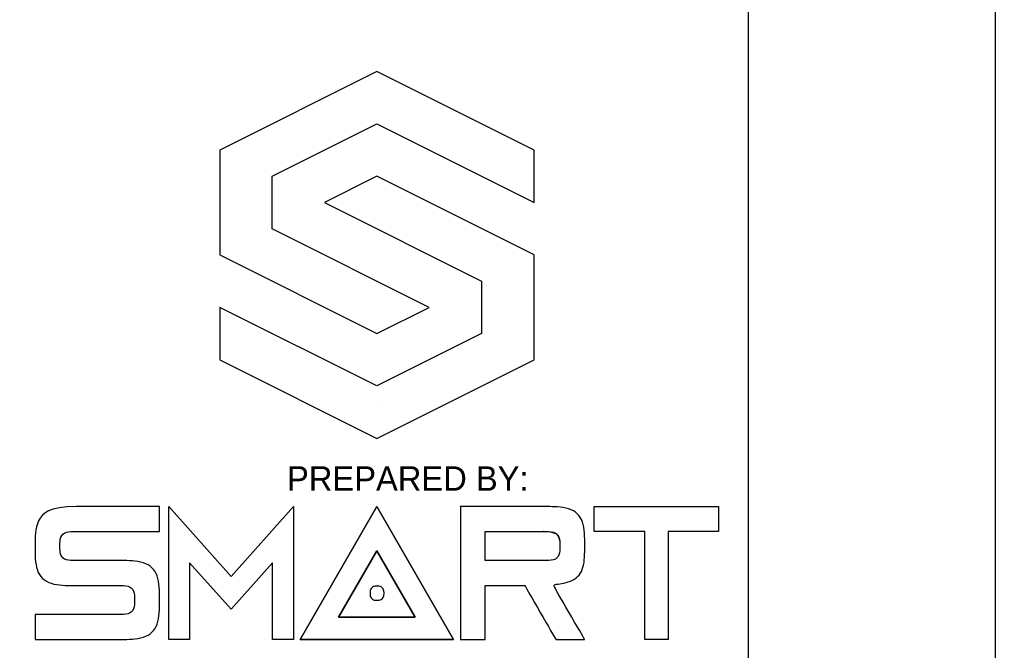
# Model space of a CAD drawing. Extents: x 0 to 34, y 0 to 22.
# Drawn here: x 32.028 to 34, y 3.5 to 4.774 of the extents above; entities that cross this region are included whole.
import ezdxf

# ---------------------------------------------------------------- set-up
doc = ezdxf.new("R2010")
doc.units = 0
for name, color, linetype in [('BORDER', 7, 'Continuous'), ('SH_Border', 7, 'Continuous'), ('SH_Cut_Line', 7, 'Continuous'), ('SH_Data', 7, 'Continuous')]:
    doc.layers.add(name, color=color, linetype=linetype)

msp = doc.modelspace()

# ---------------------------------------------------------------- linework, layer by layer
at = {"layer": 'BORDER'}
for p, q in [((32.75, 4.6694), (32.4325, 4.5106)), ((33.0676, 4.5106), (32.75, 4.6694)), ((32.5383, 4.4577), (32.75, 4.5635)), ((32.75, 4.5635), (33.0676, 4.4047)), ((32.4325, 4.5106), (32.4325, 4.2989)), ((33.0676, 4.4047), (33.0676, 4.5106)), ((32.5383, 4.3518), (32.5383, 4.4577)), ((32.75, 4.4577), (32.6442, 4.4047)), ((33.0676, 4.2989), (32.75, 4.4577)), ((32.6442, 4.4047), (32.9617, 4.246)), ((32.8559, 4.193), (32.5383, 4.3518)), ((32.4325, 4.2989), (32.75, 4.1401)), ((33.0676, 4.0872), (33.0676, 4.2989)), ((32.9617, 4.246), (32.9617, 4.1401)), ((32.75, 4.0343), (32.4325, 4.193)), ((32.4325, 4.193), (32.4325, 4.0872)), ((32.75, 4.1401), (32.8559, 4.193)), ((32.9617, 4.1401), (32.75, 4.0343)), ((32.4325, 4.0872), (32.75, 3.9284)), ((32.75, 3.9284), (33.0676, 4.0872)), ((32.3299, 3.5224), (32.3299, 3.7905)), ((32.3299, 3.7905), (32.4556, 3.6496)), ((32.4556, 3.6496), (32.5813, 3.7905)), ((32.5813, 3.7905), (32.5813, 3.5224)), ((33.1892, 3.7403), (33.1892, 3.7905)), ((33.1892, 3.7905), (33.4406, 3.7905)), ((33.4406, 3.7905), (33.4406, 3.7403)), ((33.2913, 3.7403), (33.1892, 3.7403)), ((33.2913, 3.5224), (33.2913, 3.7403)), ((33.4406, 3.7403), (33.3385, 3.7403)), ((33.3385, 3.7403), (33.3385, 3.5224)), ((32.3718, 3.6771), (32.3718, 3.5224)), ((32.4556, 3.5832), (32.3718, 3.6771)), ((32.5394, 3.6771), (32.4556, 3.5832)), ((32.5394, 3.5224), (32.5394, 3.6771)), ((32.3718, 3.5224), (32.3299, 3.5224)), ((32.5813, 3.5224), (32.5394, 3.5224)), ((33.3385, 3.5224), (33.2913, 3.5224))]:
    msp.add_line(p, q, dxfattribs=at)
for points in [[(32.75, 4.6694), (32.4325, 4.5106), (32.4325, 4.2989), (32.75, 4.1401), (32.8559, 4.193), (32.5383, 4.3518), (32.5383, 4.4577), (32.75, 4.5635), (33.0676, 4.4047), (33.0676, 4.5106), (32.75, 4.6694)], [(32.75, 3.9284), (33.0676, 4.0872), (33.0676, 4.2989), (32.75, 4.4577), (32.6442, 4.4047), (32.9617, 4.246), (32.9617, 4.1401), (32.75, 4.0343), (32.4325, 4.193), (32.4325, 4.0872), (32.75, 3.9284)], [(32.3718, 3.6771), (32.3718, 3.5224), (32.3299, 3.5224), (32.3299, 3.7905), (32.4556, 3.6496), (32.5813, 3.7905), (32.5813, 3.5224), (32.5394, 3.5224), (32.5394, 3.6771), (32.4556, 3.5832), (32.3718, 3.6771)], [(32.5953, 3.5224), (32.75, 3.7905), (32.9047, 3.5224), (32.5953, 3.5224)], [(33.2913, 3.7403), (33.1892, 3.7403), (33.1892, 3.7905), (33.4406, 3.7905), (33.4406, 3.7403), (33.3385, 3.7403), (33.3385, 3.5224), (33.2913, 3.5224), (33.2913, 3.7403)], [(32.6726, 3.5671), (32.8274, 3.5671), (32.75, 3.7011), (32.6726, 3.5671)]]:
    msp.add_lwpolyline(points, dxfattribs=at)
for points in [[(32.9047, 3.5224), (32.75, 3.7905), (32.5953, 3.5224)], [(32.75, 3.7011), (32.8274, 3.5671), (32.6726, 3.5671)]]:
    msp.add_lwpolyline(points, close=True, dxfattribs=at)
for points, degree in [([(32.1432, 3.7905), (32.1432, 3.7905), (32.3108, 3.7905), (32.3108, 3.7905), (32.3108, 3.7905), (32.3108, 3.7403), (32.3108, 3.7403), (32.3108, 3.7403), (32.1432, 3.7403), (32.1432, 3.7403), (32.1209, 3.7403), (32.1097, 3.7305), (32.1097, 3.7109), (32.1097, 3.6914), (32.1209, 3.6816), (32.1432, 3.6816), (32.1432, 3.6816), (32.227, 3.6816), (32.227, 3.6816), (32.2829, 3.6816), (32.3108, 3.6551), (32.3108, 3.602), (32.3108, 3.5489), (32.2829, 3.5224), (32.227, 3.5224), (32.227, 3.5224), (32.0594, 3.5224), (32.0594, 3.5224), (32.0594, 3.5224), (32.0594, 3.5727), (32.0594, 3.5727), (32.0594, 3.5727), (32.227, 3.5727), (32.227, 3.5727), (32.2494, 3.5727), (32.2605, 3.5824), (32.2605, 3.602), (32.2605, 3.6215), (32.2494, 3.6313), (32.227, 3.6313), (32.227, 3.6313), (32.1432, 3.6313), (32.1432, 3.6313), (32.0874, 3.6313), (32.0594, 3.6579), (32.0594, 3.7109), (32.0594, 3.764), (32.0874, 3.7905), (32.1432, 3.7905)], 3), ([(32.1432, 3.7905), (32.1432, 3.7905), (32.3108, 3.7905), (32.3108, 3.7905), (32.3108, 3.7905), (32.3108, 3.7403), (32.3108, 3.7403), (32.3108, 3.7403), (32.1432, 3.7403), (32.1432, 3.7403), (32.1209, 3.7403), (32.1097, 3.7305), (32.1097, 3.7109), (32.1097, 3.6914), (32.1209, 3.6816), (32.1432, 3.6816), (32.1432, 3.6816), (32.227, 3.6816), (32.227, 3.6816), (32.2829, 3.6816), (32.3108, 3.6551), (32.3108, 3.602), (32.3108, 3.5489), (32.2829, 3.5224), (32.227, 3.5224), (32.227, 3.5224), (32.0594, 3.5224), (32.0594, 3.5224), (32.0594, 3.5224), (32.0594, 3.5727), (32.0594, 3.5727), (32.0594, 3.5727), (32.227, 3.5727), (32.227, 3.5727), (32.2494, 3.5727), (32.2605, 3.5824), (32.2605, 3.602), (32.2605, 3.6215), (32.2494, 3.6313), (32.227, 3.6313), (32.227, 3.6313), (32.1432, 3.6313), (32.1432, 3.6313), (32.0874, 3.6313), (32.0594, 3.6579), (32.0594, 3.7109), (32.0594, 3.764), (32.0874, 3.7905), (32.1432, 3.7905)], 3), ([(32.9188, 3.7905), (32.9188, 3.7905), (32.9188, 3.5224), (32.9188, 3.5224)], 2), ([(32.9188, 3.5224), (32.9188, 3.5224), (32.969, 3.5224), (32.969, 3.5224), (32.969, 3.5224), (32.969, 3.6313), (32.969, 3.6313), (32.969, 3.6313), (33.0488, 3.6313), (33.0488, 3.6313), (33.0488, 3.6313), (33.1117, 3.5224), (33.1117, 3.5224), (33.1117, 3.5224), (33.1698, 3.5224), (33.1698, 3.5224), (33.1698, 3.5224), (33.1061, 3.6327), (33.1061, 3.6327), (33.1488, 3.6385), (33.1701, 3.6646), (33.1701, 3.7109), (33.1701, 3.764), (33.1422, 3.7905), (33.0863, 3.7905), (33.0863, 3.7905), (32.9188, 3.7905), (32.9188, 3.7905)], 3), ([(32.9188, 3.7905), (32.9188, 3.7905), (33.0863, 3.7905), (33.0863, 3.7905), (33.1422, 3.7905), (33.1701, 3.764), (33.1701, 3.7109), (33.1701, 3.6646), (33.1488, 3.6385), (33.1061, 3.6327), (33.1061, 3.6327), (33.1698, 3.5224), (33.1698, 3.5224), (33.1698, 3.5224), (33.1117, 3.5224), (33.1117, 3.5224), (33.1117, 3.5224), (33.0488, 3.6313), (33.0488, 3.6313), (33.0488, 3.6313), (32.969, 3.6313), (32.969, 3.6313), (32.969, 3.6313), (32.969, 3.5224), (32.969, 3.5224), (32.969, 3.5224), (32.9188, 3.5224), (32.9188, 3.5224), (32.9188, 3.5224), (32.9188, 3.7905), (32.9188, 3.7905)], 3), ([(32.969, 3.7403), (32.969, 3.7403), (33.0863, 3.7403), (33.0863, 3.7403)], 2), ([(33.0863, 3.7403), (33.1087, 3.7403), (33.1199, 3.7305), (33.1199, 3.7109), (33.1199, 3.6914), (33.1087, 3.6816), (33.0863, 3.6816), (33.0863, 3.6816), (32.969, 3.6816), (32.969, 3.6816), (32.969, 3.6816), (32.969, 3.7403), (32.969, 3.7403)], 3), ([(32.969, 3.7403), (32.969, 3.7403), (32.969, 3.6816), (32.969, 3.6816), (32.969, 3.6816), (33.0863, 3.6816), (33.0863, 3.6816), (33.1087, 3.6816), (33.1199, 3.6914), (33.1199, 3.7109), (33.1199, 3.7305), (33.1087, 3.7403), (33.0863, 3.7403), (33.0863, 3.7403), (32.969, 3.7403), (32.969, 3.7403)], 3), ([(32.7649, 3.6157), (32.7649, 3.6078), (32.7585, 3.6014), (32.7506, 3.6014), (32.7427, 3.6014), (32.7363, 3.6078), (32.7363, 3.6157), (32.7363, 3.6236), (32.7427, 3.63), (32.7506, 3.63), (32.7585, 3.63), (32.7649, 3.6236), (32.7649, 3.6157)], 3), ([(32.7649, 3.6157), (32.7649, 3.6078), (32.7585, 3.6014), (32.7506, 3.6014), (32.7427, 3.6014), (32.7363, 3.6078), (32.7363, 3.6157), (32.7363, 3.6236), (32.7427, 3.63), (32.7506, 3.63), (32.7585, 3.63), (32.7649, 3.6236), (32.7649, 3.6157)], 3)]:
    msp.add_open_spline(points, degree=degree, dxfattribs=at)
at = {"layer": 'SH_Border'}
msp.add_lwpolyline([(1.5, 21.5), (33.5, 21.5), (33.5, 0.5), (1.5, 0.5)], close=True, dxfattribs=at)
at = {"layer": 'SH_Cut_Line'}
msp.add_lwpolyline([(0, 0), (34, 0), (34, 22), (0, 22)], close=True, dxfattribs=at)
at = {"layer": 'SH_Data'}
msp.add_line((32.75, 4), (32.75, 4), dxfattribs=at)

# ---------------------------------------------------------------- texts
at = {"layer": 'BORDER'}
msp.add_text('PREPARED BY:', height=0.049387, dxfattribs=at).set_placement((32.5685, 3.8226))

doc.saveas('drawing.dxf')
